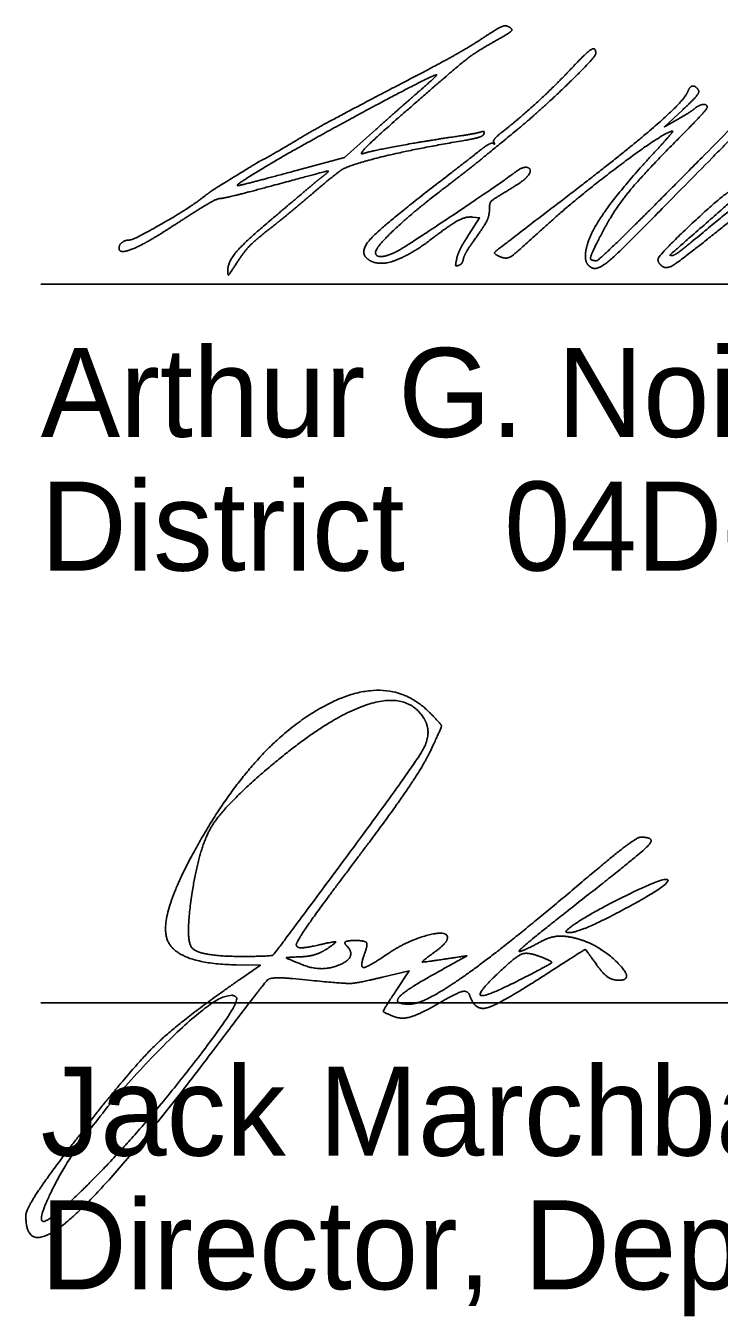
# Model space of a CAD drawing. Extents: x 0 to 34, y 0 to 22.
# Drawn here: x 24.504 to 25.594, y 7.177 to 9.205 of the extents above; entities that cross this region are included whole.
import ezdxf

# ---------------------------------------------------------------- set-up
doc = ezdxf.new("R2010")
doc.units = 0
doc.layers.add('SH_Data', color=7, linetype='Continuous')
doc.layers.add('SH_Text', color=7, linetype='Continuous')

msp = doc.modelspace()

# ---------------------------------------------------------------- linework, layer by layer
at = {"layer": 'SH_Data'}
for p, q in [((24.5279, 8.7985), (28.0279, 8.7985)), ((24.5279, 7.6691), (28.0279, 7.6691))]:
    msp.add_line(p, q, dxfattribs=at)
at = {"layer": 'SH_Text'}
for p, q in [((24.9902, 7.8741), (24.9902, 7.8741)), ((25.3555, 7.7842), (25.3555, 7.7842)), ((25.3107, 7.7426), (25.3107, 7.7426))]:
    msp.add_line(p, q, dxfattribs=at)
for points in [[(25.5283, 9.0574), (25.508, 9.0459), (25.5362, 9.0722)], [(25.0546, 9.0417), (25.005, 8.9976), (24.9235, 8.9756)], [(25.2068, 8.904), (25.2174, 8.9026), (25.2007, 8.8768)], [(24.8425, 7.7072), (24.8732, 7.7284), (24.8354, 7.729)], [(25.0855, 7.6873), (25.1067, 7.7197), (25.0649, 7.7096)]]:
    msp.add_lwpolyline(points, dxfattribs=at)
for points in [[(25.2602, 9.2043), (25.2566, 9.2056), (25.2411, 9.1978), (25.2227, 9.1854)], [(25.239, 9.1789), (25.2643, 9.1928), (25.2706, 9.2003), (25.2602, 9.2043)], [(25.7754, 9.1954), (25.7371, 9.1671), (25.6966, 9.1288), (25.567, 8.9978)], [(25.2227, 9.1854), (25.2054, 9.1738), (25.1545, 9.1451), (25.1094, 9.1216)], [(25.1166, 9.0834), (25.1813, 9.1398), (25.2132, 9.1647), (25.239, 9.1789)], [(25.4001, 9.161), (25.4001, 9.1718), (25.3854, 9.1629), (25.3623, 9.1382)], [(25.2755, 9.0405), (25.3133, 9.0717), (25.4001, 9.1556), (25.4001, 9.161)], [(25.583, 8.9972), (25.6555, 9.0713), (25.724, 9.1389), (25.7351, 9.1475)], [(24.946, 9.0205), (25.023, 9.0633), (25.1484, 9.1292), (25.15, 9.1276)], [(25.15, 9.1276), (25.1506, 9.127), (25.1405, 9.1174), (25.1276, 9.1062)], [(25.3623, 9.1382), (25.3371, 9.1112), (25.2812, 9.0598), (25.2526, 9.0374)], [(25.1094, 9.1216), (25.0334, 9.0821), (24.9544, 9.0397), (24.94, 9.0309)], [(25.1276, 9.1062), (25.1147, 9.095), (25.0818, 9.066), (25.0546, 9.0417)], [(25.5614, 9.1034), (25.557, 9.1106), (25.5476, 9.1093), (25.5446, 9.1011)], [(25.5446, 9.1011), (25.5393, 9.0869), (25.4454, 9.0056), (25.3507, 8.9332)], [(25.5362, 9.0722), (25.5538, 9.0886), (25.5633, 9.1004), (25.5614, 9.1034)], [(25.0346, 9.0039), (25.0261, 9.0011), (25.0617, 9.0357), (25.1166, 9.0834)], [(25.5271, 9.0244), (25.5535, 9.051), (25.5751, 9.0744), (25.5751, 9.0763)], [(25.5551, 9.0743), (25.5516, 9.0714), (25.5395, 9.0637), (25.5283, 9.0574)], [(25.5751, 9.0763), (25.5751, 9.0816), (25.5623, 9.0804), (25.5551, 9.0743)], [(24.94, 9.0309), (24.923, 9.0205), (24.878, 8.9943), (24.877, 8.9943)], [(24.999, 8.9771), (25.0109, 8.9857), (25.116, 9.0114), (25.1911, 9.024)], [(25.1699, 9.0291), (25.1265, 9.0226), (25.0463, 9.0077), (25.0346, 9.0039)], [(25.1558, 8.9448), (25.1948, 8.9747), (25.2224, 8.9968), (25.2755, 9.0405)], [(25.2184, 9.0375), (25.2142, 9.0362), (25.1924, 9.0324), (25.1699, 9.0291)], [(25.1911, 9.024), (25.2091, 9.0271), (25.2232, 9.0316), (25.2242, 9.0346)], [(25.2242, 9.0346), (25.2254, 9.0382), (25.2235, 9.0391), (25.2184, 9.0375)], [(25.2526, 9.0374), (25.2443, 9.0309), (25.2386, 9.0238), (25.24, 9.0215)], [(25.3182, 8.8871), (25.3693, 8.934), (25.5094, 9.039), (25.5207, 9.039)], [(25.4056, 8.871), (25.4253, 8.91), (25.471, 8.9678), (25.5271, 9.0244)], [(25.5207, 9.039), (25.5219, 9.039), (25.5098, 9.0248), (25.4938, 9.0075)], [(24.8372, 8.9535), (24.8327, 8.9535), (24.8991, 8.9944), (24.946, 9.0205)], [(25.2147, 9.0061), (25.2036, 8.9973), (25.1844, 8.9824), (25.1721, 8.9729)], [(25.2387, 9.0198), (25.2366, 9.0211), (25.2258, 9.015), (25.2147, 9.0061)], [(25.24, 9.0215), (25.2414, 9.0193), (25.2408, 9.0185), (25.2387, 9.0198)], [(25.4938, 9.0075), (25.4347, 8.9436), (25.3838, 8.8671), (25.3838, 8.8425)], [(24.877, 8.9943), (24.8764, 8.9943), (24.866, 8.9882), (24.854, 8.9808)], [(25.3986, 8.8233), (25.409, 8.8233), (25.4545, 8.8662), (25.583, 8.9972)], [(25.567, 8.9978), (25.4786, 8.9084), (25.404, 8.8353), (25.4013, 8.8354)], [(24.854, 8.9808), (24.8026, 8.9493), (24.7951, 8.9444), (24.7789, 8.932)], [(24.9235, 8.9756), (24.8787, 8.9635), (24.8399, 8.9535), (24.8372, 8.9535)], [(24.8924, 8.9535), (24.9731, 8.9754), (24.9835, 8.9773), (24.9705, 8.9675)], [(24.9507, 8.9375), (24.9706, 8.9545), (24.9923, 8.9723), (24.999, 8.9771)], [(24.9705, 8.9675), (24.9661, 8.9641), (24.9587, 8.9582), (24.9543, 8.9543)], [(25.1721, 8.9729), (25.0673, 8.8926), (25.025, 8.8466), (25.0458, 8.8355)], [(25.2731, 8.9743), (25.2545, 8.9599), (25.1005, 8.8569), (25.0878, 8.8503)], [(25.2586, 8.9439), (25.2726, 8.9524), (25.2863, 8.9615), (25.2891, 8.9643)], [(25.2891, 8.9643), (25.3018, 8.9766), (25.2876, 8.9855), (25.2731, 8.9743)], [(24.8096, 8.9332), (24.8138, 8.9332), (24.8511, 8.9423), (24.8924, 8.9535)], [(24.9543, 8.9543), (24.9498, 8.9505), (24.9239, 8.9286), (24.8966, 8.9057)], [(25.054, 8.8487), (25.054, 8.8565), (25.1122, 8.9114), (25.1558, 8.9448)], [(25.2331, 8.9184), (25.2331, 8.9265), (25.2384, 8.9317), (25.2586, 8.9439)], [(25.6135, 8.9454), (25.6063, 8.9454), (25.4979, 8.844), (25.4978, 8.8373)], [(25.6859, 8.9558), (25.6653, 8.9553), (25.6339, 8.9343), (25.5531, 8.867)], [(25.5805, 8.9005), (25.6185, 8.9337), (25.6271, 8.9454), (25.6135, 8.9454)], [(24.7789, 8.932), (24.7597, 8.9173), (24.6737, 8.868), (24.6673, 8.868)], [(24.7551, 8.9026), (24.7809, 8.9194), (24.8054, 8.9332), (24.8096, 8.9332)], [(24.8957, 8.892), (24.9061, 8.9001), (24.9308, 8.9206), (24.9507, 8.9375)], [(25.3507, 8.9332), (25.2454, 8.8527), (25.2383, 8.8461), (25.2512, 8.8411)], [(24.6891, 8.8619), (24.6996, 8.8674), (24.7292, 8.8858), (24.7551, 8.9026)], [(24.8966, 8.9057), (24.8512, 8.8675), (24.8219, 8.8341), (24.8219, 8.8205)], [(25.1395, 8.8677), (25.17, 8.8912), (25.1961, 8.9053), (25.2068, 8.904)], [(25.2068, 8.8645), (25.2253, 8.8904), (25.2331, 8.9065), (25.2331, 8.9184)], [(25.5896, 8.8805), (25.6356, 8.9173), (25.6415, 8.9209), (25.646, 8.9147)], [(24.8362, 8.8324), (24.8484, 8.8511), (24.866, 8.8687), (24.8957, 8.892)], [(25.2512, 8.8411), (25.2605, 8.8376), (25.2749, 8.8475), (25.3182, 8.8871)], [(25.5206, 8.8437), (25.5159, 8.8439), (25.5173, 8.8452), (25.5805, 8.9005)], [(24.6673, 8.868), (24.6604, 8.868), (24.6509, 8.8605), (24.6509, 8.855)], [(24.6509, 8.855), (24.6509, 8.8485), (24.6705, 8.852), (24.6891, 8.8619)], [(25.0644, 8.8314), (25.0769, 8.8314), (25.1183, 8.8514), (25.1395, 8.8677)], [(25.2007, 8.8768), (25.1915, 8.8625), (25.1828, 8.8454), (25.1815, 8.8386)], [(25.1919, 8.8378), (25.1927, 8.8421), (25.1994, 8.8541), (25.2068, 8.8645)], [(25.4013, 8.8354), (25.3911, 8.8356), (25.3921, 8.8442), (25.4056, 8.871)], [(25.5025, 8.8284), (25.5097, 8.8211), (25.5314, 8.8342), (25.5896, 8.8805)], [(25.5531, 8.867), (25.5377, 8.8542), (25.523, 8.8437), (25.5206, 8.8437)], [(25.0878, 8.8503), (25.0724, 8.8424), (25.054, 8.8415), (25.054, 8.8487)], [(25.3838, 8.8425), (25.3838, 8.8373), (25.386, 8.8308), (25.3887, 8.8281)], [(24.8219, 8.8205), (24.8219, 8.8121), (24.8241, 8.8139), (24.8362, 8.8324)], [(25.0458, 8.8355), (25.05, 8.8332), (25.0584, 8.8314), (25.0644, 8.8314)], [(25.1815, 8.8386), (25.1796, 8.8291), (25.1803, 8.8267), (25.1847, 8.8281)], [(25.1847, 8.8281), (25.1878, 8.8292), (25.1911, 8.8335), (25.1919, 8.8378)], [(25.3887, 8.8281), (25.3914, 8.8255), (25.3959, 8.8233), (25.3986, 8.8233)], [(25.4978, 8.8373), (25.4978, 8.835), (25.4999, 8.8309), (25.5025, 8.8284)], [(24.7789, 7.9249), (24.8651, 8.0752), (25.0732, 8.1913), (25.1389, 8.1256)], [(25.1299, 8.1164), (25.104, 8.1584), (24.9779, 8.1173), (24.8825, 8.0357)], [(24.9902, 7.8741), (25.1115, 8.0376), (25.144, 8.0938), (25.1299, 8.1164)], [(25.1389, 8.1256), (25.1577, 8.1068), (25.1577, 8.1018), (25.1394, 8.0634)], [(25.1394, 8.0634), (25.1284, 8.0404), (25.0767, 7.9648), (25.0245, 7.8955)], [(24.8825, 8.0357), (24.8159, 7.9786), (24.7771, 7.9145), (24.766, 7.8433)], [(25.369, 7.8514), (25.4194, 7.8942), (25.4649, 7.9294), (25.4701, 7.9295)], [(25.4701, 7.9295), (25.495, 7.93), (25.4716, 7.9044), (25.3857, 7.8372)], [(24.8354, 7.729), (24.7375, 7.7307), (24.7141, 7.8119), (24.7789, 7.9249)], [(25.0245, 7.8955), (24.9722, 7.8261), (24.9295, 7.7654), (24.9295, 7.7607)], [(24.844, 7.7422), (24.8907, 7.7422), (24.8953, 7.7463), (24.9902, 7.8741)], [(25.1076, 7.6672), (25.1307, 7.6672), (25.2567, 7.756), (25.369, 7.8514)], [(25.3555, 7.7842), (25.3759, 7.8021), (25.5079, 7.8679), (25.5131, 7.8627)], [(25.5131, 7.8627), (25.5193, 7.8566), (25.3767, 7.7797), (25.359, 7.7797)], [(24.766, 7.8433), (24.7545, 7.7699), (24.776, 7.7422), (24.844, 7.7422)], [(25.3857, 7.8372), (25.2925, 7.7642), (25.271, 7.7426), (25.315, 7.7661)], [(25.0086, 7.7589), (25.004, 7.7635), (25.0103, 7.7672), (25.0225, 7.7672)], [(25.0225, 7.7672), (25.037, 7.7672), (25.0422, 7.7608), (25.0375, 7.7484)], [(25.0736, 7.7466), (25.1025, 7.7664), (25.167, 7.7839), (25.167, 7.7719)], [(25.167, 7.7719), (25.167, 7.7674), (25.1572, 7.7566), (25.1453, 7.7479)], [(25.315, 7.7661), (25.3276, 7.7729), (25.3515, 7.775), (25.3681, 7.7708)], [(25.359, 7.7797), (25.3542, 7.7797), (25.3526, 7.7817), (25.3555, 7.7842)], [(25.3681, 7.7708), (25.4042, 7.7616), (25.4625, 7.7047), (25.4358, 7.7047)], [(24.9295, 7.7607), (24.9295, 7.7559), (24.9449, 7.7556), (24.9638, 7.76)], [(24.9795, 7.7553), (24.9692, 7.7483), (24.9495, 7.7421), (24.9357, 7.7416)], [(24.9399, 7.7289), (24.9698, 7.7169), (25.026, 7.7415), (25.0086, 7.7589)], [(24.9638, 7.76), (24.9894, 7.7659), (24.9934, 7.7647), (24.9795, 7.7553)], [(25.0375, 7.7484), (25.0285, 7.7252), (25.0414, 7.7245), (25.0736, 7.7466)], [(25.1453, 7.7479), (25.1264, 7.7341), (25.1284, 7.7328), (25.161, 7.7377)], [(25.3107, 7.7426), (25.2935, 7.7489), (25.277, 7.7438), (25.2576, 7.7261)], [(25.4011, 7.7294), (25.3843, 7.7534), (25.3822, 7.753), (25.3165, 7.7106)], [(24.9357, 7.7416), (24.9133, 7.7407), (24.9138, 7.7394), (24.9399, 7.7289)], [(25.161, 7.7377), (25.1977, 7.7432), (25.1976, 7.743), (25.1522, 7.7179)], [(25.2576, 7.7261), (25.2133, 7.6856), (25.2246, 7.6767), (25.2826, 7.7063)], [(25.2826, 7.7063), (25.329, 7.73), (25.3325, 7.7346), (25.3107, 7.7426)], [(25.4358, 7.7047), (25.4262, 7.7047), (25.4106, 7.7158), (25.4011, 7.7294)], [(24.5916, 7.465), (24.6692, 7.5654), (24.7493, 7.6427), (24.8425, 7.7072)], [(24.9237, 7.7073), (24.8903, 7.7106), (24.8786, 7.7001), (24.8019, 7.5984)], [(25.0649, 7.7096), (25.0246, 7.6998), (25.0023, 7.6995), (24.9237, 7.7073)], [(25.1522, 7.7179), (25.1011, 7.6897), (25.0814, 7.6672), (25.1076, 7.6672)], [(25.3165, 7.7106), (25.2476, 7.6662), (25.2101, 7.6565), (25.202, 7.6809)], [(25.0843, 7.6473), (25.0661, 7.6542), (25.0662, 7.6579), (25.0855, 7.6873)], [(25.202, 7.6809), (25.1991, 7.6894), (25.1799, 7.6842), (25.1508, 7.6671)], [(24.8354, 7.6779), (24.8145, 7.6988), (24.596, 7.4732), (24.5497, 7.3828)], [(24.6198, 7.4016), (24.6874, 7.4706), (24.8431, 7.6702), (24.8354, 7.6779)], [(25.1508, 7.6671), (25.1252, 7.652), (25.0953, 7.643), (25.0843, 7.6473)], [(24.8019, 7.5984), (24.6496, 7.3964), (24.5045, 7.2677), (24.5045, 7.3347)], [(24.5045, 7.3347), (24.5045, 7.3443), (24.5437, 7.403), (24.5916, 7.465)], [(24.5497, 7.3828), (24.5184, 7.3219), (24.55, 7.3303), (24.6198, 7.4016)]]:
    msp.add_open_spline(points, degree=2, dxfattribs=at)

# ---------------------------------------------------------------- texts
for s, p in [('Arthur G. Noirot Jr., P.E.', (24.5279, 8.5585)), ('District       Deputy Director', (24.5279, 8.3485)), ('              04', (24.5279, 8.3485)), ('Jack Marchbanks, PhD', (24.5279, 7.4291)), ('Director, Department of Transportation', (24.5279, 7.2191))]:
    msp.add_text(s, height=0.14, dxfattribs=at).set_placement(p)

doc.saveas('drawing.dxf')
